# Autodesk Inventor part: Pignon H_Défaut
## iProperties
Shininess: 64.0
Length Units: 11269
Angle Units: 11279
Time Units: 11290
Mass Units: 11283
Length Display Precision: 3
Angle Display Precision: 2
Compacted: True
Part Number: Pignon H_Défaut
Document SubType Name: Modeling
Created: 2006-01
Material: Par défaut
Designer: Fricot
Density: 0.0
Volumn: 0.0
Area: 0.0
PropertySet Name: Model Information
Control State: 0
Master: False
Checked Out: False
Author: Fricot
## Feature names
1. Base1
